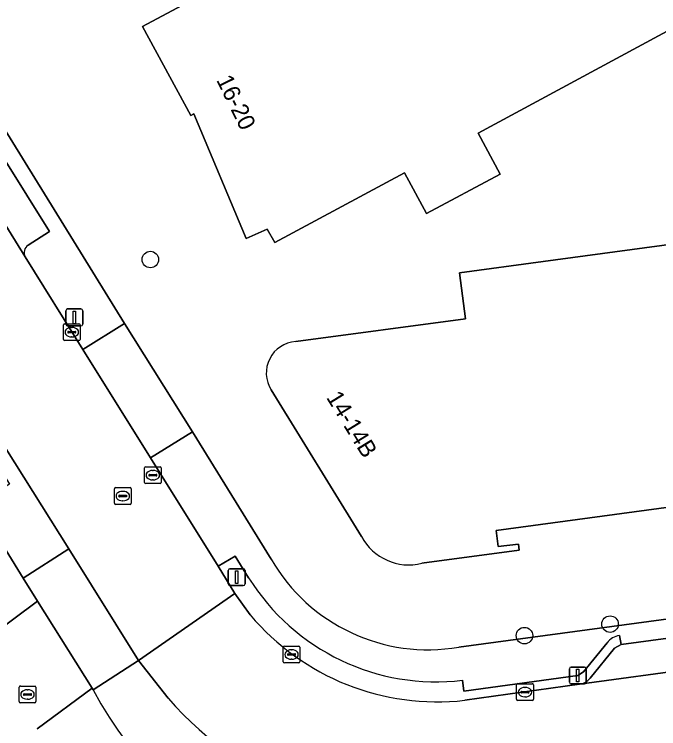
# Model space of a CAD drawing. Extents: x 158455 to 159797, y 387218 to 388672.
# Drawn here: x 158871.25 to 158909.44, y 387452.85 to 387495.18 of the extents above; entities that cross this region are included whole.
import ezdxf

# ---------------------------------------------------------------- set-up
doc = ezdxf.new("R2010")
doc.units = 0
for name, color, linetype in [('IMGEO_Boom', 7, 'Continuous'), ('IMGEO_Erf', 7, 'Continuous'), ('IMGEO_Kolk', 7, 'Continuous'), ('IMGEO_Lichtmast', 7, 'Continuous'), ('IMGEO_Pand', 7, 'Continuous'), ('IMGEO_Pand_nummerreeks', 7, 'Continuous'), ('IMGEO_Parkeervlak_open', 7, 'Continuous'), ('IMGEO_Rijbaan_lokaal_gesloten', 7, 'Continuous'), ('IMGEO_Rijbaan_lokaal_open', 7, 'Continuous'), ('IMGEO_Rioolput', 7, 'Continuous'), ('IMGEO_Voetpad_open', 7, 'Continuous')]:
    doc.layers.add(name, color=color, linetype=linetype)

msp = doc.modelspace()

# ---------------------------------------------------------------- linework, layer by layer
at = {"layer": 'IMGEO_Boom'}
for centre in [(158879.317, 387480.652), (158906.559, 387459.044), (158901.484, 387458.366)]:
    msp.add_circle(centre, 0.489, dxfattribs=at)
at = {"layer": 'IMGEO_Erf'}
for points in [[(158910.681, 387494.573), (158898.749, 387488.149), (158900.055, 387485.717), (158895.687, 387483.369), (158894.367, 387485.79), (158886.683, 387481.656), (158886.246, 387482.453), (158885, 387481.898), (158881.89, 387489.276), (158881.717, 387489.193), (158878.849, 387494.465), (158883.251, 387496.837), (158889.122, 387500), (158911.389, 387511.996), (158903.617, 387526.376), (158901.241, 387530.775), (158918.572, 387540.133)], [(158817.674, 387419.378), (158827.832, 387426.967), (158834.448, 387431.91), (158853.054, 387445.81), (158872.628, 387460.413), (158871.776, 387461.775), (158869.054, 387466.18), (158867.865, 387468.105), (158855.534, 387488.061), (158855.344, 387488.369), (158855.598, 387488.53), (158843.07, 387508.642), (158842.309, 387509.96), (158841.704, 387511.33), (158840.764, 387514.306), (158840.483, 387515.393), (158836.029, 387514.802)], [(158854.791, 387514.318), (158860.99, 387504.36), (158864.727, 387498.394), (158866.115, 387496.102), (158865.95, 387496.039), (158867.678, 387493.237), (158869.993, 387489.451), (158877.792, 387476.863), (158881.804, 387470.44), (158886.478, 387462.89)], [(158887.928, 387475.792), (158898, 387477.138), (158897.636, 387479.867), (158902.592, 387480.534), (158917.386, 387482.524), (158922.456, 387483.206), (158922.527, 387482.333), (158922.735, 387482.364), (158928.491, 387471.834), (158930.889, 387467.446)], [(158897.588, 387457.682), (158930.651, 387462.152), (158938.394, 387463.195), (158955.888, 387465.567), (158962.696, 387466.48), (158963.921, 387466.644), (158965.858, 387466.905), (158981.668, 387469.041), (158988.546, 387469.989), (158989.691, 387470.147), (158994.651, 387470.867), (158999.62, 387471.71), (159006.133, 387473.558)], [(158891.823, 387464.24), (158886.476, 387472.928)], [(158930.889, 387467.446), (158924.084, 387466.503), (158923.909, 387467.857), (158899.801, 387464.599), (158899.932, 387463.646), (158901.123, 387463.789), (158901.178, 387463.425), (158895.408, 387462.651)], [(158875.925, 387455.143), (158875.861, 387455.245), (158872.617, 387452.848)]]:
    msp.add_lwpolyline(points, dxfattribs=at)
for centre, radius, start, end in [((158888.053, 387473.929), 1.867, 93.8291, 212.4024), ((158894.636, 387465.748), 3.192, 208.1996, 283.9912), ((158895.766, 387468.249), 10.723, 209.9835, 279.7853), ((158895.756, 387465.7), 22.466, 208.0279, 282.052)]:
    msp.add_arc(centre, radius, start, end, dxfattribs=at)
at = {"layer": 'IMGEO_Kolk'}
for p, q in [((158874.159, 387475.92), (158874.159, 387476.772)), ((158874.234, 387476.846), (158875.086, 387476.846)), ((158874.647, 387476.626), (158874.672, 387476.626)), ((158875.16, 387476.772), (158875.16, 387475.92)), ((158874.418, 387476.34), (158874.418, 387476.352)), ((158874.856, 387476.303), (158874.458, 387476.303)), ((158874.461, 387476.389), (158874.859, 387476.389)), ((158874.902, 387476.352), (158874.902, 387476.34)), ((158875.086, 387475.846), (158874.234, 387475.846)), ((158874.67, 387476.066), (158874.645, 387476.066)), ((158887.182, 387456.819), (158887.182, 387457.671)), ((158887.257, 387457.745), (158888.109, 387457.745)), ((158888.183, 387457.671), (158888.183, 387456.819)), ((158887.441, 387457.239), (158887.441, 387457.251)), ((158887.879, 387457.202), (158887.481, 387457.202)), ((158887.484, 387457.288), (158887.882, 387457.288)), ((158887.67, 387457.525), (158887.695, 387457.525)), ((158887.925, 387457.251), (158887.925, 387457.239)), ((158888.109, 387456.745), (158887.257, 387456.745)), ((158887.693, 387456.965), (158887.668, 387456.965)), ((158901.089, 387455.517), (158901.941, 387455.517)), ((158901.014, 387454.591), (158901.014, 387455.443)), ((158901.316, 387455.06), (158901.714, 387455.06)), ((158901.502, 387455.297), (158901.527, 387455.297)), ((158902.015, 387455.443), (158902.015, 387454.591)), ((158901.273, 387455.011), (158901.273, 387455.023)), ((158901.711, 387454.974), (158901.313, 387454.974)), ((158901.525, 387454.737), (158901.5, 387454.737)), ((158901.757, 387455.023), (158901.757, 387455.011)), ((158901.941, 387454.517), (158901.089, 387454.517))]:
    msp.add_line(p, q, dxfattribs=at)
for points in [[(158874.159, 387475.92), (158874.159, 387476.772)], [(158874.234, 387476.846), (158875.086, 387476.846)], [(158875.16, 387476.772), (158875.16, 387475.92)], [(158875.086, 387475.846), (158874.234, 387475.846)], [(158887.182, 387456.819), (158887.182, 387457.671)], [(158887.257, 387457.745), (158888.109, 387457.745)], [(158888.183, 387457.671), (158888.183, 387456.819)], [(158888.109, 387456.745), (158887.257, 387456.745)], [(158901.089, 387455.517), (158901.941, 387455.517)], [(158901.014, 387454.591), (158901.014, 387455.443)], [(158902.015, 387455.443), (158902.015, 387454.591)], [(158901.941, 387454.517), (158901.089, 387454.517)]]:
    msp.add_lwpolyline(points, dxfattribs=at)
for centre, radius, start, end in [((158874.236, 387476.77), 0.0765, 91.552, 178.448), ((158874.236, 387476.77), 0.0765, 91.552, 178.448), ((158875.084, 387476.77), 0.0765, 1.552, 88.448), ((158875.084, 387476.77), 0.0765, 1.552, 88.448), ((158874.458, 387476.349), 0.0403, 85.8775, 175.7526), ((158874.455, 387476.339), 0.0366, 178.938, 274.7102), ((158874.859, 387476.346), 0.043, 264.8664, 352.4533), ((158874.863, 387476.351), 0.0386, 1.7309, 96.639), ((158874.236, 387475.922), 0.0765, 181.552, 268.448), ((158874.236, 387475.922), 0.0765, 181.552, 268.448), ((158875.084, 387475.922), 0.0765, 271.552, 358.448), ((158875.084, 387475.922), 0.0765, 271.552, 358.448), ((158887.259, 387457.669), 0.0765, 91.552, 178.448), ((158887.259, 387457.669), 0.0765, 91.552, 178.448), ((158888.107, 387457.669), 0.0765, 1.552, 88.448), ((158888.107, 387457.669), 0.0765, 1.552, 88.448), ((158887.481, 387457.248), 0.0403, 85.8775, 175.7526), ((158887.478, 387457.238), 0.0366, 178.938, 274.7102), ((158887.882, 387457.245), 0.043, 264.8664, 352.4533), ((158887.886, 387457.25), 0.0386, 1.7309, 96.639), ((158887.259, 387456.821), 0.0765, 181.552, 268.448), ((158887.259, 387456.821), 0.0765, 181.552, 268.448), ((158888.107, 387456.821), 0.0765, 271.552, 358.448), ((158888.107, 387456.821), 0.0765, 271.552, 358.448), ((158901.091, 387455.441), 0.0765, 91.552, 178.448), ((158901.091, 387455.441), 0.0765, 91.552, 178.448), ((158901.939, 387455.441), 0.0765, 1.552, 88.448), ((158901.939, 387455.441), 0.0765, 1.552, 88.448), ((158901.313, 387455.02), 0.0403, 85.8775, 175.7526), ((158901.718, 387455.022), 0.0386, 1.7309, 96.639), ((158901.31, 387455.01), 0.0366, 178.938, 274.7102), ((158901.714, 387455.017), 0.043, 264.8664, 352.4533), ((158901.091, 387454.593), 0.0765, 181.552, 268.448), ((158901.091, 387454.593), 0.0765, 181.552, 268.448), ((158901.939, 387454.593), 0.0765, 271.552, 358.448), ((158901.939, 387454.593), 0.0765, 271.552, 358.448)]:
    msp.add_arc(centre, radius, start, end, dxfattribs=at)
for centre, major_axis, ratio, start_param, end_param in [((158874.646, 387476.346), (-0.387, 0.002), 0.722429, 4.712389, 7.853982), ((158874.671, 387476.346), (-0.39, 0.002), 0.717154, 1.570796, 4.712389), ((158887.669, 387457.245), (-0.387, 0.002), 0.722429, 4.712389, 7.853982), ((158887.694, 387457.245), (-0.39, 0.002), 0.717154, 1.570796, 4.712389), ((158901.501, 387455.017), (-0.387, 0.002), 0.722429, 4.712389, 7.853982), ((158901.526, 387455.017), (-0.39, 0.002), 0.717154, 1.570796, 4.712389)]:
    msp.add_ellipse(centre, major_axis=major_axis, ratio=ratio, start_param=start_param, end_param=end_param, dxfattribs=at)
at = {"layer": 'IMGEO_Lichtmast'}
for p, q in [((158874.314, 387476.82), (158874.314, 387477.62)), ((158874.314, 387477.62), (158874.314, 387476.82)), ((158874.414, 387477.72), (158875.204, 387477.72)), ((158875.204, 387477.72), (158874.414, 387477.72)), ((158875.304, 387477.62), (158875.304, 387476.82)), ((158875.304, 387476.82), (158875.304, 387477.62)), ((158875.204, 387476.72), (158874.414, 387476.72)), ((158874.414, 387476.72), (158875.204, 387476.72)), ((158883.935, 387461.429), (158883.935, 387462.229)), ((158883.935, 387462.229), (158883.935, 387461.429)), ((158884.035, 387462.329), (158884.825, 387462.329)), ((158884.825, 387462.329), (158884.035, 387462.329)), ((158884.925, 387462.229), (158884.925, 387461.429)), ((158884.925, 387461.429), (158884.925, 387462.229)), ((158884.825, 387461.329), (158884.035, 387461.329)), ((158884.035, 387461.329), (158884.825, 387461.329)), ((158904.147, 387455.598), (158904.147, 387456.398)), ((158904.147, 387456.398), (158904.147, 387455.598)), ((158904.247, 387456.498), (158905.037, 387456.498)), ((158905.037, 387456.498), (158904.247, 387456.498)), ((158905.137, 387456.398), (158905.137, 387455.598)), ((158905.137, 387455.598), (158905.137, 387456.398)), ((158905.037, 387455.498), (158904.247, 387455.498)), ((158904.247, 387455.498), (158905.037, 387455.498))]:
    msp.add_line(p, q, dxfattribs=at)
for points in [[(158874.734, 387477.595), (158874.884, 387477.595), (158874.884, 387476.845), (158874.734, 387476.845), (158874.734, 387477.595)], [(158884.355, 387462.204), (158884.505, 387462.204), (158884.505, 387461.454), (158884.355, 387461.454), (158884.355, 387462.204)], [(158904.567, 387456.373), (158904.717, 387456.373), (158904.717, 387455.623), (158904.567, 387455.623), (158904.567, 387456.373)]]:
    msp.add_lwpolyline(points, dxfattribs=at)
for centre, start, end in [((158874.414, 387477.62), 90, 180), ((158874.414, 387477.62), 90, 180), ((158875.204, 387477.62), 0, 90), ((158875.204, 387477.62), 360, 90), ((158874.414, 387476.82), 180, 270), ((158874.414, 387476.82), 180, 270), ((158875.204, 387476.82), 270, 0), ((158875.204, 387476.82), 270, 0), ((158884.035, 387462.229), 90, 180), ((158884.035, 387462.229), 90, 180), ((158884.825, 387462.229), 0, 90), ((158884.825, 387462.229), 360, 90), ((158884.035, 387461.429), 180, 270), ((158884.035, 387461.429), 180, 270), ((158884.825, 387461.429), 270, 0), ((158884.825, 387461.429), 270, 0), ((158904.247, 387456.398), 90, 180), ((158904.247, 387456.398), 90, 180), ((158905.037, 387456.398), 0, 90), ((158905.037, 387456.398), 360, 90), ((158904.247, 387455.598), 180, 270), ((158904.247, 387455.598), 180, 270), ((158905.037, 387455.598), 270, 0), ((158905.037, 387455.598), 270, 0)]:
    msp.add_arc(centre, 0.1, start, end, dxfattribs=at)
at = {"layer": 'IMGEO_Pand'}
for points in [[(158918.572, 387540.133), (158901.241, 387530.775), (158903.617, 387526.376), (158911.389, 387511.996), (158889.122, 387500), (158883.251, 387496.837), (158878.849, 387494.465), (158881.717, 387489.193), (158881.89, 387489.276), (158885, 387481.898), (158886.246, 387482.453), (158886.683, 387481.656), (158894.367, 387485.79), (158895.687, 387483.369), (158900.055, 387485.717), (158898.749, 387488.149), (158910.681, 387494.573)], [(158895.408, 387462.651), (158901.178, 387463.425), (158901.123, 387463.789), (158899.932, 387463.646), (158899.801, 387464.599), (158923.909, 387467.857), (158924.084, 387466.503), (158930.889, 387467.446), (158928.491, 387471.834), (158922.735, 387482.364), (158922.527, 387482.333), (158922.456, 387483.206), (158917.386, 387482.524), (158902.592, 387480.534), (158897.636, 387479.867), (158898, 387477.138), (158887.928, 387475.792)], [(158886.476, 387472.928), (158891.823, 387464.24)]]:
    msp.add_lwpolyline(points, dxfattribs=at)
for centre, radius, start, end in [((158888.053, 387473.929), 1.867, 93.8291, 212.4024), ((158894.636, 387465.748), 3.192, 208.1996, 283.9912)]:
    msp.add_arc(centre, radius, start, end, dxfattribs=at)
at = {"layer": 'IMGEO_Parkeervlak_open'}
for points in [[(158872.076, 387481.503), (158873.336, 387482.31), (158869.196, 387488.923), (158867.506, 387487.881), (158871.89, 387480.802)], [(158930.321, 387459.235), (158928.479, 387460.501), (158928.046, 387460.65), (158907.215, 387457.847), (158906.813, 387457.615), (158905.375, 387455.847)], [(158904.755, 387455.484), (158911.727, 387456.43), (158931.027, 387459.048)]]:
    msp.add_lwpolyline(points, dxfattribs=at)
for centre, radius, start, end in [((158872.367, 387481.051), 0.538, 122.7668, 207.5129), ((158904.6, 387456.459), 0.987, 279.0141, 321.6824)]:
    msp.add_arc(centre, radius, start, end, dxfattribs=at)
at = {"layer": 'IMGEO_Rijbaan_lokaal_gesloten'}
msp.add_lwpolyline([(158851.893, 387513.001), (158846.014, 387509.226), (158870.648, 387469.607), (158870.748, 387469.446), (158874.475, 387463.509), (158878.61, 387456.886), (158884.328, 387460.865), (158883.328, 387462.471), (158879.331, 387468.895), (158875.318, 387475.314), (158871.89, 387480.802), (158867.506, 387487.881), (158865.145, 387491.667), (158862.032, 387496.673), (158858.337, 387502.653)], close=True, dxfattribs=at)
for points in [[(159000.491, 387467.294), (158995.33, 387466.262), (158911.961, 387454.948), (158911.727, 387456.43), (158904.755, 387455.484), (158897.945, 387454.534)], [(158885.238, 387459.589), (158884.328, 387460.865), (158878.61, 387456.886), (158880.363, 387454.65)]]:
    msp.add_lwpolyline(points, dxfattribs=at)
for centre, radius, start, end in [((158896.307, 387468.915), 14.474, 220.1146, 276.4989), ((158895.992, 387468.359), 20.79, 221.2558, 278.1232)]:
    msp.add_arc(centre, radius, start, end, dxfattribs=at)
at = {"layer": 'IMGEO_Rijbaan_lokaal_open'}
msp.add_lwpolyline([(158872.617, 387452.848), (158875.861, 387455.245), (158872.628, 387460.413), (158853.054, 387445.81), (158834.448, 387431.91), (158827.832, 387426.967), (158817.674, 387419.378)], dxfattribs=at)
at = {"layer": 'IMGEO_Rioolput'}
for p, q in [((158878.963, 387467.447), (158878.963, 387468.299)), ((158879.038, 387468.373), (158879.89, 387468.373)), ((158879.451, 387468.153), (158879.476, 387468.153)), ((158879.964, 387468.299), (158879.964, 387467.447)), ((158879.222, 387467.867), (158879.222, 387467.879)), ((158879.66, 387467.83), (158879.262, 387467.83)), ((158879.265, 387467.916), (158879.663, 387467.916)), ((158879.706, 387467.879), (158879.706, 387467.867)), ((158879.89, 387467.373), (158879.038, 387467.373)), ((158879.474, 387467.593), (158879.449, 387467.593)), ((158877.182, 387466.209), (158877.182, 387467.061)), ((158877.257, 387467.135), (158878.109, 387467.135)), ((158877.67, 387466.915), (158877.695, 387466.915)), ((158878.183, 387467.061), (158878.183, 387466.209)), ((158877.441, 387466.629), (158877.441, 387466.641)), ((158877.879, 387466.592), (158877.481, 387466.592)), ((158877.484, 387466.678), (158877.882, 387466.678)), ((158877.925, 387466.641), (158877.925, 387466.629)), ((158878.109, 387466.135), (158877.257, 387466.135)), ((158877.693, 387466.355), (158877.668, 387466.355)), ((158871.535, 387454.453), (158871.535, 387455.305)), ((158871.61, 387455.379), (158872.462, 387455.379)), ((158872.023, 387455.159), (158872.048, 387455.159)), ((158872.536, 387455.305), (158872.536, 387454.453)), ((158871.794, 387454.873), (158871.794, 387454.885)), ((158872.232, 387454.836), (158871.834, 387454.836)), ((158871.837, 387454.922), (158872.235, 387454.922)), ((158872.278, 387454.885), (158872.278, 387454.873)), ((158872.462, 387454.379), (158871.61, 387454.379)), ((158872.046, 387454.599), (158872.021, 387454.599))]:
    msp.add_line(p, q, dxfattribs=at)
for points in [[(158878.963, 387467.447), (158878.963, 387468.299)], [(158879.038, 387468.373), (158879.89, 387468.373)], [(158879.964, 387468.299), (158879.964, 387467.447)], [(158879.89, 387467.373), (158879.038, 387467.373)], [(158877.182, 387466.209), (158877.182, 387467.061)], [(158877.257, 387467.135), (158878.109, 387467.135)], [(158878.183, 387467.061), (158878.183, 387466.209)], [(158878.109, 387466.135), (158877.257, 387466.135)], [(158871.535, 387454.453), (158871.535, 387455.305)], [(158871.61, 387455.379), (158872.462, 387455.379)], [(158872.536, 387455.305), (158872.536, 387454.453)], [(158872.462, 387454.379), (158871.61, 387454.379)]]:
    msp.add_lwpolyline(points, dxfattribs=at)
for centre, radius, start, end in [((158879.04, 387468.297), 0.0765, 91.552, 178.448), ((158879.04, 387468.297), 0.0765, 91.552, 178.448), ((158879.888, 387468.297), 0.0765, 1.552, 88.448), ((158879.888, 387468.297), 0.0765, 1.552, 88.448), ((158879.262, 387467.876), 0.0403, 85.8775, 175.7526), ((158879.259, 387467.866), 0.0366, 178.938, 274.7102), ((158879.663, 387467.873), 0.043, 264.8664, 352.4533), ((158879.667, 387467.878), 0.0386, 1.7309, 96.639), ((158879.04, 387467.449), 0.0765, 181.552, 268.448), ((158879.04, 387467.449), 0.0765, 181.552, 268.448), ((158879.888, 387467.449), 0.0765, 271.552, 358.448), ((158879.888, 387467.449), 0.0765, 271.552, 358.448), ((158877.259, 387467.059), 0.0765, 91.552, 178.448), ((158877.259, 387467.059), 0.0765, 91.552, 178.448), ((158878.107, 387467.059), 0.0765, 1.552, 88.448), ((158878.107, 387467.059), 0.0765, 1.552, 88.448), ((158877.481, 387466.638), 0.0403, 85.8775, 175.7526), ((158877.478, 387466.628), 0.0366, 178.938, 274.7102), ((158877.882, 387466.635), 0.043, 264.8664, 352.4533), ((158877.886, 387466.64), 0.0386, 1.7309, 96.639), ((158877.259, 387466.211), 0.0765, 181.552, 268.448), ((158877.259, 387466.211), 0.0765, 181.552, 268.448), ((158878.107, 387466.211), 0.0765, 271.552, 358.448), ((158878.107, 387466.211), 0.0765, 271.552, 358.448), ((158871.612, 387455.303), 0.0765, 91.552, 178.448), ((158871.612, 387455.303), 0.0765, 91.552, 178.448), ((158872.46, 387455.303), 0.0765, 1.552, 88.448), ((158872.46, 387455.303), 0.0765, 1.552, 88.448), ((158871.834, 387454.882), 0.0403, 85.8775, 175.7526), ((158871.831, 387454.872), 0.0366, 178.938, 274.7102), ((158872.235, 387454.879), 0.043, 264.8664, 352.4533), ((158872.239, 387454.884), 0.0386, 1.7309, 96.639), ((158871.612, 387454.455), 0.0765, 181.552, 268.448), ((158871.612, 387454.455), 0.0765, 181.552, 268.448), ((158872.46, 387454.455), 0.0765, 271.552, 358.448), ((158872.46, 387454.455), 0.0765, 271.552, 358.448)]:
    msp.add_arc(centre, radius, start, end, dxfattribs=at)
for centre, major_axis, ratio, start_param, end_param in [((158879.45, 387467.873), (-0.387, 0.002), 0.722429, 4.712389, 7.853982), ((158879.475, 387467.873), (-0.39, 0.002), 0.717154, 1.570796, 4.712389), ((158877.669, 387466.635), (-0.387, 0.002), 0.722429, 4.712389, 7.853982), ((158877.694, 387466.635), (-0.39, 0.002), 0.717154, 1.570796, 4.712389), ((158872.022, 387454.879), (-0.387, 0.002), 0.722429, 4.712389, 7.853982), ((158872.047, 387454.879), (-0.39, 0.002), 0.717154, 1.570796, 4.712389)]:
    msp.add_ellipse(centre, major_axis=major_axis, ratio=ratio, start_param=start_param, end_param=end_param, dxfattribs=at)
at = {"layer": 'IMGEO_Voetpad_open'}
for points in [[(158840.764, 387514.306), (158841.704, 387511.33), (158842.309, 387509.96), (158843.07, 387508.642), (158855.598, 387488.53), (158855.344, 387488.369), (158855.534, 387488.061), (158867.865, 387468.105), (158869.78, 387469.254), (158870.966, 387467.333), (158869.054, 387466.18), (158871.776, 387461.775), (158874.475, 387463.509), (158870.748, 387469.446), (158870.295, 387469.159), (158870.033, 387469.406), (158867.805, 387469.996)], [(158871.89, 387480.802), (158875.318, 387475.314), (158877.792, 387476.863), (158869.993, 387489.451), (158869.196, 387488.923), (158873.336, 387482.31), (158872.076, 387481.503)], [(158886.478, 387462.89), (158881.804, 387470.44), (158879.331, 387468.895), (158883.328, 387462.471), (158884.334, 387463.078), (158885.14, 387461.796)], [(158885.14, 387461.796), (158884.334, 387463.078), (158883.328, 387462.471), (158884.328, 387460.865), (158885.238, 387459.589)], [(158928.728, 387461.03), (158930.592, 387459.704), (158930.971, 387459.582), (158930.651, 387462.152), (158897.588, 387457.682)], [(158907.116, 387458.366), (158907.215, 387457.847), (158928.046, 387460.65), (158927.967, 387461.172)], [(158905.375, 387455.847), (158906.813, 387457.615), (158907.215, 387457.847), (158907.116, 387458.366)], [(158897.822, 387455.721), (158897.89, 387455.078), (158904.642, 387455.998), (158904.993, 387456.219), (158906.383, 387457.942)], [(158906.383, 387457.942), (158904.993, 387456.219), (158904.642, 387455.998), (158897.89, 387455.078), (158897.822, 387455.721)], [(158880.363, 387454.65), (158878.61, 387456.886), (158875.925, 387455.143)], [(158897.945, 387454.534), (158904.755, 387455.484)]]:
    msp.add_lwpolyline(points, dxfattribs=at)
for points in [[(158877.792, 387476.863), (158875.318, 387475.314), (158879.331, 387468.895), (158881.804, 387470.44)], [(158872.628, 387460.413), (158875.861, 387455.245), (158875.925, 387455.143), (158878.61, 387456.886), (158874.475, 387463.509), (158871.776, 387461.775)]]:
    msp.add_lwpolyline(points, close=True, dxfattribs=at)
for centre, radius, start, end in [((158872.367, 387481.051), 0.538, 122.7668, 207.5129), ((158895.766, 387468.249), 10.723, 209.9835, 279.7853), ((158896.251, 387468.717), 13.09, 211.9166, 276.8922), ((158896.251, 387468.717), 13.09, 211.9166, 276.8922), ((158896.307, 387468.915), 14.474, 220.1146, 276.4989), ((158907.269, 387457.256), 1.12, 97.8376, 142.2565), ((158907.269, 387457.256), 1.12, 97.8376, 142.2565), ((158904.6, 387456.459), 0.987, 279.0141, 321.6824), ((158895.756, 387465.7), 22.466, 208.0279, 282.052), ((158895.992, 387468.359), 20.79, 221.2558, 278.1232)]:
    msp.add_arc(centre, radius, start, end, dxfattribs=at)

# ---------------------------------------------------------------- texts
at = {"layer": 'IMGEO_Pand_nummerreeks'}
for s, rotation, p in [('16-20', 296.0797, (158883.205, 387491.296)), ('14-14B', 301.6101, (158889.711, 387472.479))]:
    msp.add_text(s, height=1, rotation=rotation, dxfattribs=at).set_placement(p)

doc.saveas('drawing.dxf')
